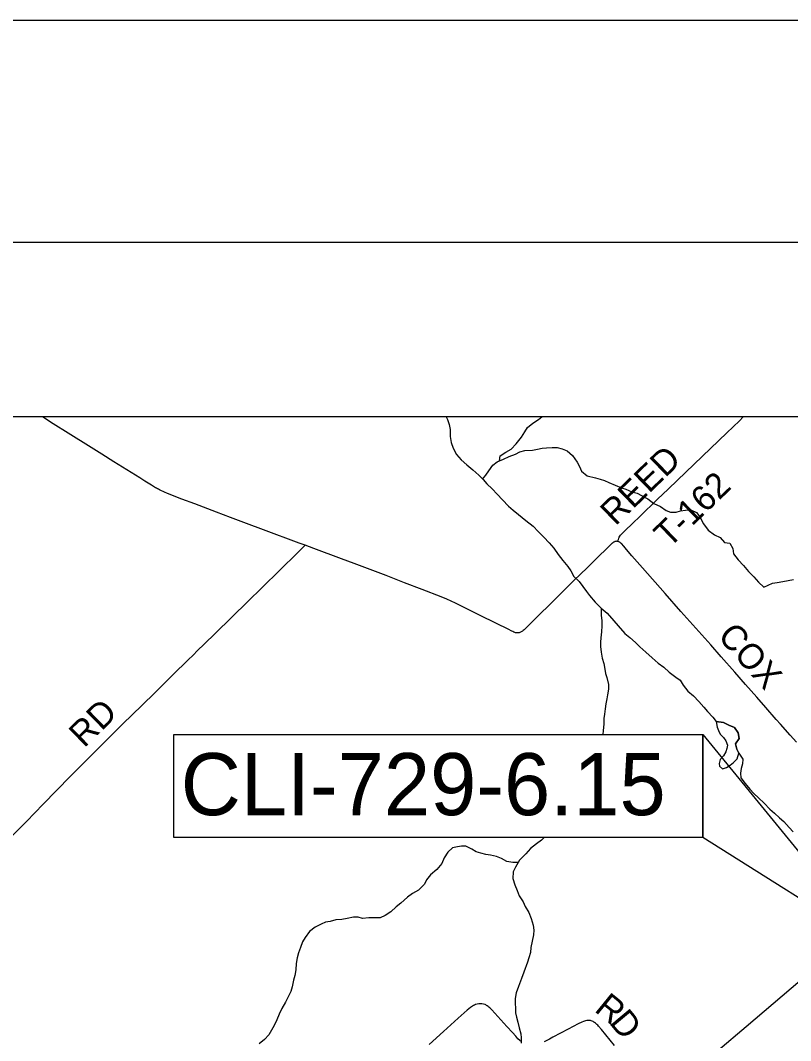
# Model space of a CAD drawing. Extents: x 0 to 34, y 0 to 22.
# Drawn here: x 27.52 to 29.255, y 19.7 to 22 of the extents above; entities that cross this region are included whole.
import ezdxf

# ---------------------------------------------------------------- set-up
doc = ezdxf.new("R2010")
doc.units = 0
for name, color, linetype in [('GM_X_Corporation', 7, 'Continuous'), ('GM_X_County_Road', 7, 'Continuous'), ('GM_X_County_Road_Text', 7, 'Continuous'), ('GM_X_Major_River', 7, 'Continuous'), ('GM_X_Minor_Lake', 7, 'Continuous'), ('GM_X_Minor_River', 7, 'Continuous'), ('GM_X_State_Route', 7, 'Continuous'), ('GM_X_Township_Road', 7, 'Continuous'), ('GM_X_Township_Road_Text', 7, 'Continuous'), ('SH_Border', 7, 'Continuous'), ('SH_Cut_Line', 7, 'Continuous'), ('SH_Text', 7, 'Continuous')]:
    doc.layers.add(name, color=color, linetype=linetype)

msp = doc.modelspace()

# ---------------------------------------------------------------- linework, layer by layer
at = {"layer": 'GM_X_Corporation'}
for points in [[(31.5875, 16.2767), (31.5875, 21.1059), (24.7875, 21.1059), (24.7875, 14.3059), (28.9316, 14.3059), (29.0116, 14.3654), (30.2271, 15.2782), (30.4064, 15.4161), (30.5426, 15.5161)], [(31.5875, 16.2767), (31.5875, 21.1059), (25.6086, 21.1059), (25.0178, 20.9472), (26.0175, 20.4289), (26.9873, 19.9283), (27.122, 19.8586), (27.3085, 19.7612), (27.7955, 19.0474), (28.3618, 18.3058), (29.4482, 16.7745), (29.7308, 16.376), (30.2965, 15.5727), (30.4064, 15.4161), (30.5426, 15.5161)]]:
    msp.add_lwpolyline(points, close=True, dxfattribs=at)
at = {"layer": 'GM_X_County_Road'}
for points in [[(28.161, 20.8169), (28.148, 20.8218), (28.0676, 20.8515), (28.0293, 20.866), (27.9931, 20.8792), (27.9612, 20.8915), (27.9123, 20.9099), (27.8832, 20.9208), (27.8589, 20.9304), (27.8498, 20.9341), (27.8458, 20.9358), (27.844, 20.9366), (27.841, 20.938), (27.8377, 20.9394), (27.8349, 20.9407), (27.833, 20.9417), (27.8307, 20.9429), (27.8286, 20.9439), (27.826, 20.9453), (27.824, 20.9465), (27.8147, 20.9519), (27.7999, 20.9611), (27.7885, 20.9685), (27.73, 21.005), (27.7032, 21.022), (27.679, 21.0372), (27.6274, 21.0695), (27.5938, 21.0907), (27.5693, 21.1059)], [(28.8654, 20.8254), (28.8633, 20.8256), (28.8618, 20.8255), (28.8605, 20.8253), (28.8594, 20.825), (28.8584, 20.8245), (28.8567, 20.8236), (28.8549, 20.8224), (28.8539, 20.8216), (28.8525, 20.8206), (28.8507, 20.8189), (28.848, 20.8164), (28.8404, 20.8089), (28.8227, 20.7915), (28.7966, 20.7657), (28.7671, 20.7373), (28.7411, 20.7115), (28.7149, 20.6858), (28.6861, 20.6575), (28.6589, 20.6302), (28.6548, 20.6263), (28.6529, 20.6247), (28.6514, 20.6234), (28.6497, 20.6223), (28.6482, 20.6213), (28.6465, 20.6205), (28.645, 20.6199), (28.6434, 20.6194), (28.6414, 20.6192), (28.6388, 20.6191), (28.6356, 20.6196), (28.6337, 20.6203), (28.6319, 20.6209), (28.6293, 20.6222), (28.6268, 20.6233), (28.619, 20.6273), (28.5923, 20.6406), (28.5545, 20.6594), (28.4998, 20.6862), (28.4807, 20.695), (28.4675, 20.7005), (28.4247, 20.7173), (28.3852, 20.7323), (28.3661, 20.7396), (28.3441, 20.7482), (28.2719, 20.7753), (28.2429, 20.7863), (28.1812, 20.8094), (28.161, 20.8169)], [(29.2686, 20.3731), (29.2545, 20.3888), (29.2325, 20.4133), (29.223, 20.424), (29.1993, 20.4511), (29.1788, 20.4745), (29.1538, 20.5029), (29.1292, 20.531), (29.0988, 20.5654), (29.0753, 20.5919), (29.0551, 20.6147), (29.0081, 20.6677), (28.9726, 20.7077), (28.9218, 20.7656), (28.8977, 20.7932), (28.8856, 20.8073), (28.8796, 20.8145), (28.8742, 20.8204), (28.8726, 20.8218), (28.8714, 20.8228), (28.87, 20.8238), (28.8691, 20.8242), (28.8679, 20.8248), (28.8667, 20.8252), (28.8654, 20.8254)], [(28.6469, 19.6987), (28.6449, 19.7004), (28.6408, 19.7043), (28.6357, 19.7098), (28.6282, 19.7182), (28.6157, 19.732), (28.5889, 19.7622), (28.5821, 19.7694), (28.5797, 19.7718), (28.5772, 19.7741), (28.5752, 19.7757), (28.5734, 19.7771), (28.5717, 19.7782), (28.5698, 19.7795), (28.5681, 19.7803), (28.5666, 19.7811), (28.5632, 19.7823), (28.5597, 19.783), (28.5561, 19.7832), (28.5525, 19.7829), (28.5489, 19.7823), (28.5455, 19.7813), (28.5426, 19.7802), (28.5403, 19.7791), (28.5384, 19.7779), (28.5364, 19.7765), (28.5339, 19.7747), (28.5264, 19.7683), (28.5064, 19.7505), (28.4727, 19.7202), (28.4404, 19.6911)], [(28.8582, 19.6888), (28.829, 19.7251), (28.8227, 19.7327), (28.8208, 19.7346), (28.8188, 19.7367), (28.8173, 19.738), (28.8155, 19.7394), (28.8137, 19.7407), (28.812, 19.7419), (28.81, 19.743), (28.8079, 19.744), (28.806, 19.7446), (28.8044, 19.745), (28.8017, 19.7454), (28.7996, 19.7456), (28.7961, 19.7452), (28.7931, 19.7447), (28.7909, 19.7441), (28.7885, 19.7431), (28.7846, 19.7415), (28.7768, 19.7377), (28.7542, 19.7259), (28.7196, 19.7075), (28.7119, 19.7035), (28.6997, 19.6973)]]:
    msp.add_lwpolyline(points, dxfattribs=at)
at = {"layer": 'GM_X_Major_River'}
msp.add_lwpolyline([(28.4788, 21.1059), (28.482, 21.1), (28.4861, 21.089), (28.4879, 21.0776), (28.4882, 21.0617), (28.49, 21.0484), (28.4945, 21.0358), (28.502, 21.021), (28.513, 21.0096), (28.5255, 20.9981), (28.5391, 20.987), (28.5527, 20.9748), (28.5621, 20.9649), (28.5704, 20.9554), (28.5825, 20.9439), (28.5942, 20.9317), (28.6059, 20.9191), (28.6195, 20.905), (28.6301, 20.8962), (28.6422, 20.8863), (28.6588, 20.8726), (28.6751, 20.86), (28.6864, 20.8474), (28.6992, 20.8348), (28.7113, 20.8222), (28.7215, 20.81), (28.7317, 20.7959), (28.7422, 20.7822), (28.7536, 20.7688), (28.76, 20.7589), (28.7671, 20.7464), (28.7784, 20.7349), (28.7867, 20.7235), (28.795, 20.7128), (28.8022, 20.7033), (28.8146, 20.6888), (28.8282, 20.6751), (28.8415, 20.664)], dxfattribs=at)
at = {"layer": 'GM_X_Minor_Lake'}
for points in [[(29.0875, 20.4194), (29.0897, 20.407), (29.0926, 20.3993), (29.0963, 20.3905), (29.1039, 20.3836), (29.1095, 20.3756), (29.1132, 20.3664), (29.1116, 20.3585), (29.1096, 20.3509), (29.1037, 20.3422), (29.0964, 20.3336), (29.094, 20.3245), (29.0947, 20.3188), (29.1019, 20.313), (29.1107, 20.3159), (29.1191, 20.3211), (29.1268, 20.3271), (29.1345, 20.335), (29.1388, 20.3481)], [(29.1388, 20.3481), (29.134, 20.3567), (29.1311, 20.3693), (29.1392, 20.3813), (29.1371, 20.3935), (29.1289, 20.4061), (29.116, 20.4108), (29.1043, 20.4174), (29.0875, 20.4194)]]:
    msp.add_lwpolyline(points, dxfattribs=at)
at = {"layer": 'GM_X_Minor_River'}
for points in [[(28.599, 21.0072), (28.6009, 21.0185), (28.6132, 21.0267), (28.6258, 21.0334), (28.6366, 21.0455), (28.6486, 21.0601), (28.6567, 21.0726), (28.6625, 21.0824), (28.6744, 21.0918), (28.6875, 21.1004), (28.6947, 21.1059)], [(28.561, 20.9661), (28.5684, 20.9744), (28.575, 20.9842), (28.5843, 20.9974), (28.5939, 21.0049), (28.608, 21.0112), (28.621, 21.0168), (28.6356, 21.0219), (28.6451, 21.0275), (28.6562, 21.0304), (28.6733, 21.031), (28.6848, 21.0335), (28.6955, 21.0353), (28.7054, 21.0367), (28.7183, 21.0369), (28.729, 21.0368), (28.7403, 21.0344), (28.7521, 21.0297), (28.7641, 21.0189), (28.7742, 21.0044), (28.7798, 20.9944), (28.7839, 20.9841), (28.7971, 20.9734), (28.8156, 20.9686), (28.8259, 20.9658), (28.8357, 20.963), (28.846, 20.9584), (28.8596, 20.9525), (28.8743, 20.9459), (28.8842, 20.9431), (28.8974, 20.9369), (28.9092, 20.9341), (28.919, 20.9287), (28.9334, 20.9217), (28.9473, 20.9109), (28.9621, 20.9042), (28.9746, 20.8954), (28.9848, 20.8911), (28.997, 20.8917), (29.0073, 20.8942), (29.0183, 20.8956), (29.0305, 20.8963), (29.0434, 20.8904), (29.0509, 20.8808), (29.059, 20.8652), (29.0695, 20.851), (29.0839, 20.8402), (29.0963, 20.8343), (29.1061, 20.8232), (29.1183, 20.8216), (29.1253, 20.8093), (29.1263, 20.7971), (29.1372, 20.7837), (29.1488, 20.7714), (29.1605, 20.7576), (29.1725, 20.7457), (29.183, 20.7338), (29.1947, 20.7223), (29.2046, 20.7271), (29.2142, 20.7316), (29.2249, 20.733), (29.2378, 20.7351), (29.25, 20.7372), (29.2615, 20.7398)], [(28.8282, 20.6751), (28.8287, 20.6588), (28.8297, 20.6466), (28.8295, 20.6348), (28.829, 20.6215), (28.8277, 20.6079), (28.8272, 20.598), (28.8271, 20.5885), (28.8284, 20.5759), (28.8309, 20.5622), (28.8346, 20.5504), (28.8363, 20.5375), (28.8381, 20.528), (28.8414, 20.5184), (28.8451, 20.5028), (28.8446, 20.4926), (28.8425, 20.4797), (28.8409, 20.4702), (28.8392, 20.4592), (28.8372, 20.4482), (28.8355, 20.4357), (28.8346, 20.4262), (28.8341, 20.4136), (28.8328, 20.3988), (28.8319, 20.3904)], [(28.8415, 20.664), (28.8818, 20.6179), (28.8927, 20.6087), (28.9055, 20.5975), (28.9157, 20.5879), (28.9293, 20.5756), (28.9436, 20.5632), (28.9567, 20.5513), (28.9696, 20.5417), (28.9816, 20.5309), (28.9963, 20.5193), (29.0061, 20.5128), (29.0132, 20.5013), (29.0233, 20.4879), (29.0361, 20.4775), (29.0485, 20.4648), (29.0598, 20.4517), (29.068, 20.4422), (29.0797, 20.4291), (29.0875, 20.4194), (29.1043, 20.4174), (29.116, 20.4108), (29.1289, 20.4061), (29.1371, 20.3935), (29.1392, 20.3813), (29.1311, 20.3693), (29.134, 20.3567), (29.1388, 20.3481), (29.1474, 20.3345), (29.1465, 20.3242), (29.1441, 20.3133), (29.1425, 20.3026), (29.1431, 20.2927), (29.1525, 20.2797), (29.1637, 20.2667), (29.1723, 20.2571), (29.1829, 20.2475), (29.1957, 20.2355), (29.2081, 20.2221), (29.219, 20.2125), (29.2299, 20.2025), (29.2401, 20.194), (29.2521, 20.1806), (29.2607, 20.171)], [(28.6998, 20.1578), (28.694, 20.1519), (28.6828, 20.1433), (28.669, 20.1328), (28.6586, 20.1212), (28.6444, 20.1065), (28.635, 20.0907), (28.6303, 20.0805), (28.629, 20.0656), (28.6338, 20.0515), (28.6393, 20.0382), (28.6438, 20.0263), (28.6524, 20.0126), (28.6572, 20.0026), (28.665, 19.9885), (28.6709, 19.9751), (28.6753, 19.9606), (28.6767, 19.9489), (28.6758, 19.9382), (28.6726, 19.9242), (28.6701, 19.9098), (28.6689, 19.8988), (28.6657, 19.8867), (28.6621, 19.8768), (28.6542, 19.8541), (28.6491, 19.8397), (28.6421, 19.8223), (28.6366, 19.808), (28.6349, 19.7947), (28.6348, 19.7844), (28.635, 19.7723), (28.6353, 19.7624), (28.6378, 19.7525), (28.6407, 19.7414), (28.6436, 19.7289), (28.6472, 19.7155), (28.6483, 19.706), (28.6481, 19.6946)], [(28.6413, 20.1013), (28.6295, 20.1014), (28.6158, 20.1038), (28.6037, 20.1104), (28.5927, 20.1147), (28.5787, 20.1183), (28.5684, 20.1199), (28.557, 20.1223), (28.5468, 20.1258), (28.5366, 20.1313), (28.5234, 20.1383), (28.5139, 20.1384), (28.5043, 20.1366), (28.4936, 20.1344), (28.4825, 20.125), (28.4743, 20.1118), (28.4692, 20.0994), (28.4577, 20.0858), (28.4438, 20.0738), (28.4349, 20.0625), (28.4299, 20.0527), (28.4164, 20.0392), (28.4034, 20.0317), (28.3919, 20.0231), (28.3769, 20.01), (28.3665, 20.0014), (28.3546, 19.9905), (28.3415, 19.9819), (28.33, 19.9771), (28.316, 19.9765), (28.3046, 19.9766), (28.2905, 19.9756), (28.2806, 19.9784), (28.27, 19.9785), (28.2562, 19.9756), (28.244, 19.9731), (28.2303, 19.9721), (28.2173, 19.9688), (28.2074, 19.9667), (28.1971, 19.9626), (28.1841, 19.9555), (28.171, 19.9462), (28.161, 19.9326), (28.1555, 19.9224), (28.1508, 19.9099), (28.1465, 19.8982), (28.1433, 19.8869), (28.1408, 19.8736), (28.1403, 19.8599), (28.1382, 19.847), (28.1347, 19.8364), (28.1322, 19.8216), (28.1291, 19.811), (28.1236, 19.8001), (28.117, 19.7868), (28.1084, 19.7725), (28.1026, 19.7597), (28.0978, 19.7472), (28.0916, 19.7343), (28.0854, 19.7238), (28.0796, 19.7128), (28.0695, 19.7023), (28.0576, 19.6929)]]:
    msp.add_lwpolyline(points, dxfattribs=at)
at = {"layer": 'GM_X_State_Route'}
msp.add_lwpolyline([(29.0911, 19.6778), (29.1552, 19.7319), (29.2972, 19.8528), (29.2978, 19.8533)], dxfattribs=at)
at = {"layer": 'GM_X_Township_Road'}
for points in [[(28.8654, 20.8254), (28.8671, 20.8297), (28.8683, 20.8328), (28.8691, 20.8347), (28.8702, 20.8371), (28.8722, 20.8398), (28.882, 20.8494), (28.8998, 20.8667), (28.9154, 20.8819), (28.9552, 20.9203), (28.9791, 20.9429), (29.0005, 20.9637), (29.0749, 21.0351), (29.1116, 21.0704), (29.1399, 21.0975), (29.1487, 21.1059)], [(27.4996, 20.1602), (27.5331, 20.1943), (27.5708, 20.2331), (27.6319, 20.2958), (27.66, 20.324), (27.7118, 20.3759), (27.7504, 20.4138), (27.7931, 20.4555), (27.8231, 20.4848), (27.8634, 20.5249), (27.8977, 20.5583), (27.9086, 20.5693), (27.9188, 20.5794), (27.9339, 20.5941), (27.9592, 20.6189), (28.0321, 20.6901), (28.0641, 20.7214), (28.1438, 20.7999), (28.1553, 20.8112), (28.161, 20.8169)]]:
    msp.add_lwpolyline(points, dxfattribs=at)
at = {"layer": 'SH_Border'}
msp.add_lwpolyline([(1.5, 21.5), (33.5, 21.5), (33.5, 0.5), (1.5, 0.5)], close=True, dxfattribs=at)
at = {"layer": 'SH_Cut_Line'}
msp.add_lwpolyline([(0, 0), (34, 0), (34, 22), (0, 22)], close=True, dxfattribs=at)
at = {"layer": 'SH_Text'}
for points in [[(27.8654, 20.3904), (29.0576, 20.3904), (29.0576, 20.1578), (27.8654, 20.1578)], [(29.0576, 20.3904), (29.4485, 19.9112), (29.0576, 20.1578)]]:
    msp.add_lwpolyline(points, close=True, dxfattribs=at)

# ---------------------------------------------------------------- texts
at = {"layer": 'GM_X_County_Road_Text'}
for s, height, rotation, p in [('COX', 0.05682, 311.5589, (29.0887, 20.6106)), ('R', 0.0568, 320.8721, (28.8109, 19.7674)), ('D', 0.0568, 309.9063, (28.845, 19.74))]:
    msp.add_text(s, height=height, rotation=rotation, dxfattribs=at).set_placement(p)
at = {"layer": 'GM_X_Township_Road_Text'}
for s, rotation, p in [('REED', 44.074, (28.8603, 20.8589)), ('T-162', 43.8153, (28.9812, 20.8089)), ('RD', 44.3017, (27.6631, 20.3585))]:
    msp.add_text(s, height=0.05682, rotation=rotation, dxfattribs=at).set_placement(p)
at = {"layer": 'SH_Text'}
msp.add_text('CLI-729-6.15', height=0.14, dxfattribs=at).set_placement((27.881, 20.2082))

doc.saveas('drawing.dxf')
